// Mitsubishi GX Works2 project: 练习画三角形   PLC: FX3U/FX3UC

PROGRAM MAIN
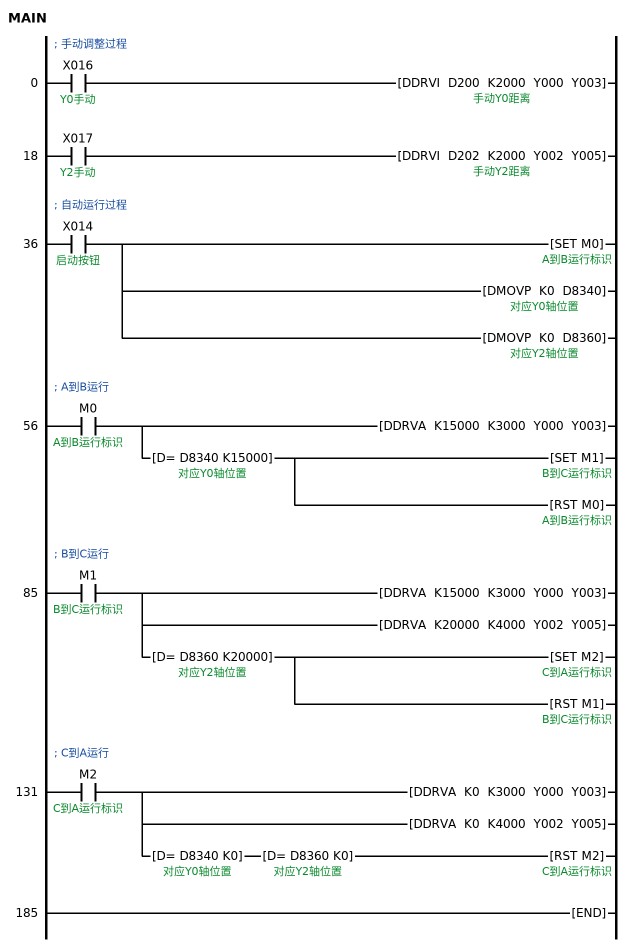
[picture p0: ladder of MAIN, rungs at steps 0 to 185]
; 手动调整过程
0     LD      X016  ; Y0手动
      DDRVI   D200 K2000 Y000 Y003  ; 手动Y0距离
18    LD      X017  ; Y2手动
      DDRVI   D202 K2000 Y002 Y005  ; 手动Y2距离
; 自动运行过程
36    LD      X014  ; 启动按钮
      SET     M0  ; A到B运行标识
      DMOVP   K0 D8340  ; 对应Y0轴位置
        [note] 定位一个Y0轴零点
      DMOVP   K0 D8360  ; 对应Y2轴位置
        [note] 定位一个Y2轴零点
; A到B运行
56    LD      M0  ; A到B运行标识
      DDRVA   K15000 K3000 Y000 Y003
        [note] Y3方向运行1.5W个脉冲，频率3000
      ANDD=   D8340 K15000  ; 对应Y0轴位置
      SET     M1  ; B到C运行标识
      RST     M0  ; A到B运行标识
; B到C运行
85    LD      M1  ; B到C运行标识
      DDRVA   K15000 K3000 Y000 Y003
        [note] 保持A到B的距离
      DDRVA   K20000 K4000 Y002 Y005
        [note] 同时向Y5方向2W个脉冲，频率4000
      ANDD=   D8360 K20000  ; 对应Y2轴位置
      SET     M2  ; C到A运行标识
      RST     M1  ; B到C运行标识
; C到A运行
131   LD      M2  ; C到A运行标识
      DDRVA   K0 K3000 Y000 Y003
        [note] Y0轴回零点
      DDRVA   K0 K4000 Y002 Y005
        [note] Y2轴回零点
      ANDD=   D8340 K0  ; 对应Y0轴位置
      ANDD=   D8360 K0  ; 对应Y2轴位置
      RST     M2  ; C到A运行标识
185   END
END_PROGRAM

// device comments not shown above
X015  ; B到C
Y001  ; 方向
D201  ; 零点
D204  ; A到B距离
D206  ; B到C距离
D208  ; A到B距离
D210  ; A到B速度
